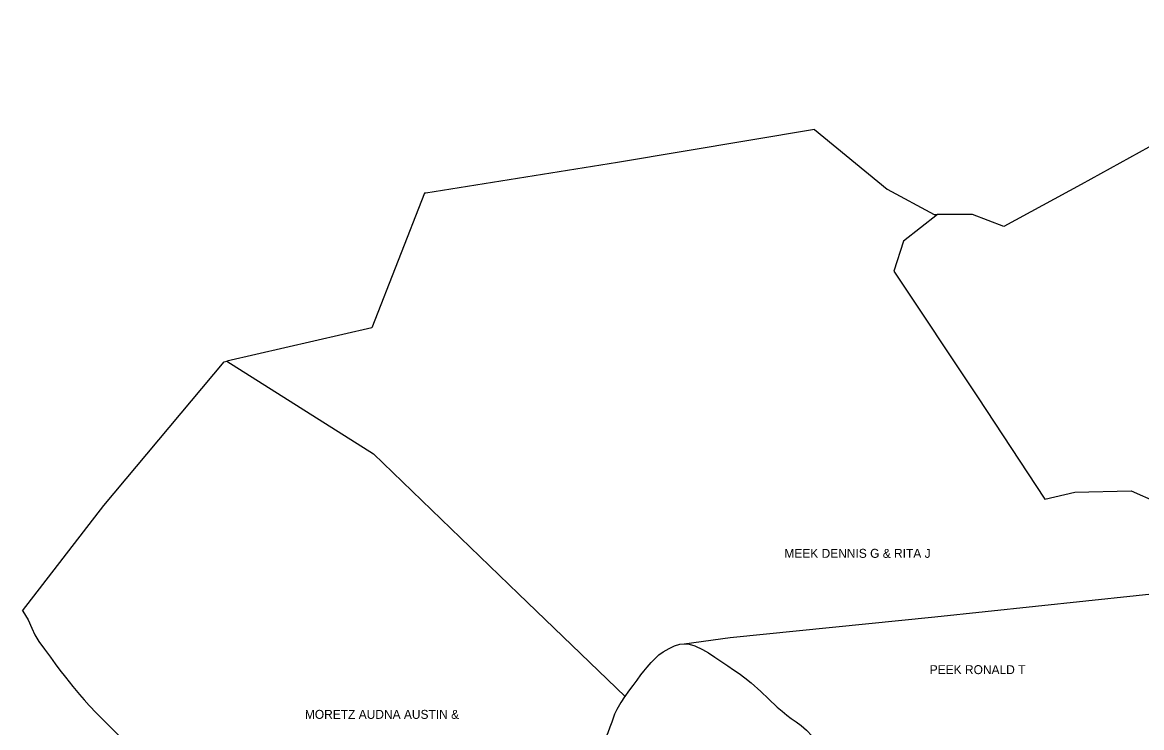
# Model space of a CAD drawing. Extents: x 1249333 to 1254314, y 856599 to 862241.
# Drawn here: x 1249839 to 1252043, y 860811 to 862200 of the extents above; entities that cross this region are included whole.
import ezdxf

# ---------------------------------------------------------------- set-up
doc = ezdxf.new("R2010")
doc.units = 0
doc.layers.add('Old_Level_12', color=7, linetype='Continuous')
doc.layers.add('Old_Level_32', color=7, linetype='Continuous')

msp = doc.modelspace()

# ---------------------------------------------------------------- linework, layer by layer
at = {"layer": 'Old_Level_12'}
for p, q in [((1251399, 861988.938), (1251542.25, 861871.313)), ((1251133.625, 860975.25), (1251142.625, 860976.438))]:
    msp.add_line(p, q, dxfattribs=at)
for points in [[(1252506.125, 862199.875), (1252228.75, 862048.438), (1251924.5, 861880.5), (1251772.125, 861797.75), (1251710.5, 861821.313), (1251641, 861821.313)], [(1251399, 861988.938), (1251010.875, 861924.063), (1250633.625, 861863.688), (1250631.375, 861863.313), (1250527.375, 861598.188), (1250242, 861532.625)], [(1251542.25, 861871.313), (1251634.625, 861821.313), (1251641, 861821.313)], [(1251641, 861821.313), (1251574.25, 861769.375), (1251555.375, 861709.75), (1251720.125, 861462.25), (1251852.5, 861261.125), (1251911.625, 861274.75), (1252022.875, 861277.5), (1252073.25, 861255.125), (1252098, 861203.188), (1252131.875, 861081.875)], [(1249839.375, 861041.375), (1250000, 861248.375), (1250236.75, 861531.438), (1250242, 861532.625)], [(1250242, 861532.625), (1250531, 861350.313), (1250816.5, 861074.813), (1251026.125, 860872.813)], [(1251142.625, 860976.438), (1251233.125, 860988.438), (1251635.75, 861029.625), (1252131.875, 861081.875)], [(1249839.375, 861041.375), (1249840.375, 861040.25), (1249850.5, 861023.25), (1249858.25, 861006.813), (1249864, 860993.813), (1249871.625, 860980.938), (1249883, 860965.438), (1249894.75, 860949.813), (1249904.125, 860936.938), (1249913.25, 860924.375), (1249924, 860910.25), (1249938.5, 860892.313), (1249951.75, 860876.625), (1249960.75, 860865.875), (1249970.625, 860854.938), (1249985.625, 860839.375), (1250000, 860825.125), (1250334.25, 860488.25)], [(1251026.125, 860872.813), (1251033.625, 860882.875), (1251042, 860894.125), (1251049.875, 860904.813), (1251057.25, 860914.875), (1251062.875, 860922.563), (1251069.375, 860930.438), (1251077.625, 860939.25), (1251085.625, 860947.563), (1251092.375, 860954.25), (1251101.125, 860960.438), (1251112.625, 860966.875), (1251123.25, 860971.938), (1251133.625, 860975.25)], [(1251142.625, 860976.438), (1251152.25, 860975.5), (1251163.5, 860972.063), (1251178.625, 860965.188), (1251190.375, 860958.25), (1251203.125, 860949.625), (1251216.625, 860940.625), (1251228.625, 860932.688), (1251239.875, 860925.25), (1251250.5, 860917.875), (1251261.75, 860909.563), (1251274.375, 860899.25), (1251293.125, 860882.5), (1251308.5, 860867.688), (1251325.875, 860851.688), (1251335.5, 860843.313), (1251344.375, 860835.875), (1251353.125, 860829.313), (1251363, 860822.75), (1251373.125, 860815.563), (1251383.5, 860806.125), (1251394.25, 860794.188)], [(1251026.125, 860872.813), (1251025.25, 860871.688), (1251017.875, 860860.875), (1251009.625, 860846.875), (1251005.125, 860837.563), (1251002.375, 860829.625), (1251000, 860822.125), (1250996.375, 860811.813), (1250992, 860800.938), (1250986.875, 860789.688), (1250982.25, 860780.688), (1250977.5, 860772.438), (1250971.625, 860762.5), (1250965.25, 860751.75)]]:
    msp.add_lwpolyline(points, dxfattribs=at)

# ---------------------------------------------------------------- texts
at = {"layer": 'Old_Level_32'}
for s, p in [('MEEK DENNIS G & RITA J', (1251339.75, 861145.563)), ('PEEK RONALD T', (1251626, 860916.563)), ('MORETZ AUDNA AUSTIN &', (1250395.625, 860828.5))]:
    msp.add_text(s, height=17.61477, dxfattribs=at).set_placement(p)

doc.saveas('drawing.dxf')
